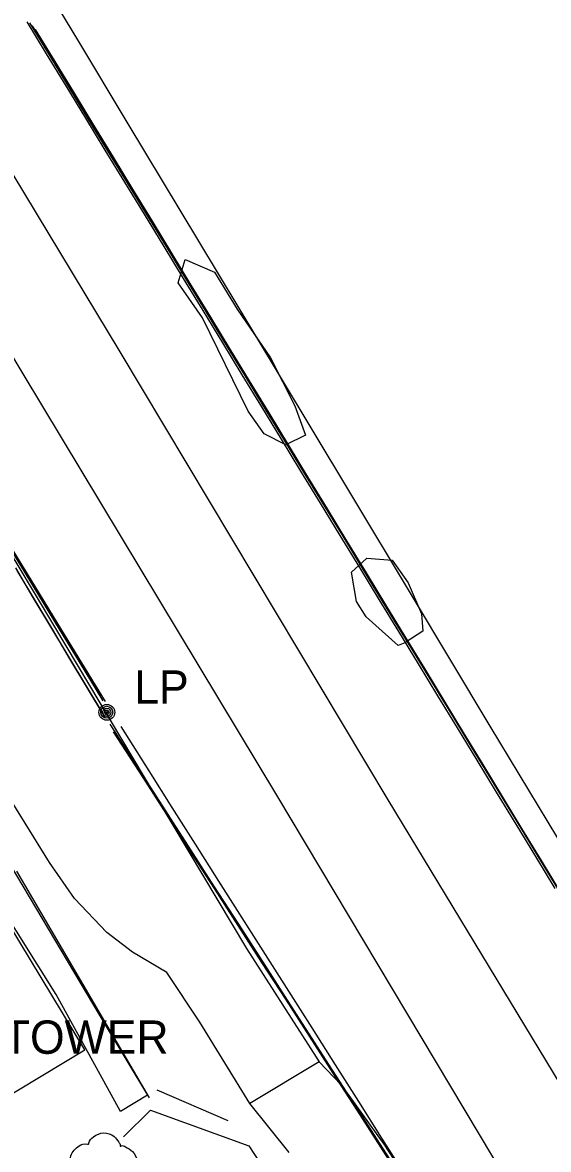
# Model space of a CAD drawing. Extents: x 368532 to 392481, y 10654822 to 10676899.
# Drawn here: x 378958.9 to 379037.9, y 10660853.5 to 10661022.5 of the extents above; entities that cross this region are included whole.
import ezdxf

# ---------------------------------------------------------------- set-up
doc = ezdxf.new("R2010")
doc.units = 0
for name, color, linetype in [('p_Catenary', 7, 'Continuous'), ('p_dtm retaining wall', 7, 'Continuous'), ('p_dtm sidewalk', 7, 'Continuous'), ('p_railroad rr control', 7, 'Continuous'), ('p_road - paved curb', 7, 'Continuous'), ('p_road conc barrier', 7, 'Continuous'), ('p_road dirt road', 7, 'Continuous'), ('p_road general road feature', 7, 'Continuous'), ('p_structure fence', 7, 'Continuous'), ('p_structure general', 7, 'Continuous'), ('p_utility general pole', 7, 'Continuous'), ('p_veg tree', 7, 'Continuous'), ('p_veg woods', 7, 'Continuous')]:
    doc.layers.add(name, color=color, linetype=linetype)

msp = doc.modelspace()

# ---------------------------------------------------------------- linework, layer by layer
at = {"layer": 'p_Catenary'}
for points in [[(378971.06, 10660920.8), (378967.51, 10660926.63), (378963.95, 10660932.46), (378960.4, 10660938.29), (378956.85, 10660944.12), (378953.29, 10660949.95), (378949.74, 10660955.79), (378946.19, 10660961.62), (378942.64, 10660967.45), (378939.08, 10660973.28), (378935.53, 10660979.11), (378931.98, 10660984.94), (378928.42, 10660990.78), (378924.87, 10660996.61), (378921.32, 10661002.44), (378917.76, 10661008.27), (378914.21, 10661014.1), (378910.66, 10661019.94), (378907.1, 10661025.77)], [(378970.65, 10660921.48), (378967.13, 10660927.25), (378963.62, 10660933.01), (378960.1, 10660938.78), (378956.59, 10660944.55), (378953.07, 10660950.32), (378949.56, 10660956.09), (378946.04, 10660961.86), (378942.53, 10660967.63), (378939.01, 10660973.4), (378935.5, 10660979.17), (378931.98, 10660984.94), (378928.47, 10660990.71), (378924.95, 10660996.48), (378921.44, 10661002.24), (378917.92, 10661008.01), (378914.41, 10661013.78), (378910.89, 10661019.55), (378907.37, 10661025.32)], [(378907.77, 10661024.85), (378911.3, 10661019.06), (378914.83, 10661013.27), (378918.36, 10661007.49), (378921.89, 10661001.7), (378925.42, 10660995.91), (378928.95, 10660990.13), (378932.48, 10660984.34), (378936.01, 10660978.56), (378939.54, 10660972.77), (378943.07, 10660966.98), (378946.6, 10660961.2), (378950.13, 10660955.41), (378953.66, 10660949.62), (378957.19, 10660943.84), (378960.72, 10660938.05), (378964.25, 10660932.27), (378967.78, 10660926.48), (378971.32, 10660920.69)], [(378959.56, 10661022.63), (378962.5, 10661017.82), (378965.44, 10661013.01), (378968.37, 10661008.19), (378971.31, 10661003.38), (378974.25, 10660998.57), (378977.18, 10660993.75), (378980.12, 10660988.94), (378983.06, 10660984.12), (378985.99, 10660979.31), (378988.93, 10660974.5), (378991.87, 10660969.68), (378994.8, 10660964.87), (378997.74, 10660960.05), (379000.68, 10660955.24), (379003.61, 10660950.43), (379006.55, 10660945.61), (379009.49, 10660940.8), (379012.42, 10660935.98), (379015.36, 10660931.17), (379018.3, 10660926.36), (379021.23, 10660921.54), (379024.17, 10660916.73), (379027.11, 10660911.91), (379030.04, 10660907.1), (379032.98, 10660902.29), (379035.92, 10660897.47), (379038.85, 10660892.66)], [(378959.98, 10661022.47), (378962.91, 10661017.67), (378965.84, 10661012.88), (378968.76, 10661008.08), (378971.69, 10661003.29), (378974.62, 10660998.49), (378977.55, 10660993.7), (378980.48, 10660988.9), (378983.41, 10660984.11), (378986.34, 10660979.31), (378989.26, 10660974.52), (378992.19, 10660969.72), (378995.12, 10660964.93), (378998.05, 10660960.13), (379000.98, 10660955.34), (379003.91, 10660950.54), (379006.84, 10660945.75), (379009.76, 10660940.95), (379012.69, 10660936.16), (379015.62, 10660931.36), (379018.55, 10660926.57), (379021.48, 10660921.77), (379024.41, 10660916.98), (379027.34, 10660912.18), (379030.26, 10660907.39), (379033.19, 10660902.59), (379036.12, 10660897.8), (379039.05, 10660893)], [(378960.36, 10661022.03), (378977.78, 10660993.45), (378981.24, 10660987.79), (378984.69, 10660982.12), (378988.14, 10660976.46), (378991.6, 10660970.8), (378995.05, 10660965.13), (378998.5, 10660959.47), (379001.96, 10660953.81), (379005.41, 10660948.14), (379008.86, 10660942.48), (379012.32, 10660936.82), (379015.77, 10660931.15), (379019.22, 10660925.49), (379022.68, 10660919.83), (379026.13, 10660914.16), (379029.58, 10660908.5), (379033.04, 10660902.84), (379036.49, 10660897.17), (379039.94, 10660891.51)], [(378960.85, 10661021.48), (378963.77, 10661016.69), (378966.69, 10661011.9), (378969.61, 10661007.1), (378972.53, 10661002.31), (378975.45, 10660997.52), (378978.37, 10660992.73), (378981.29, 10660987.93), (378984.21, 10660983.14), (378987.13, 10660978.35), (378990.05, 10660973.55), (378992.97, 10660968.76), (378995.89, 10660963.97), (378998.81, 10660959.17), (379001.73, 10660954.38), (379004.65, 10660949.59), (379007.57, 10660944.79), (379010.49, 10660940), (379013.41, 10660935.21), (379016.33, 10660930.42), (379019.25, 10660925.62), (379022.17, 10660920.83), (379025.09, 10660916.04), (379028.01, 10660911.24), (379030.93, 10660906.45), (379033.85, 10660901.66), (379036.77, 10660896.86), (379039.7, 10660892.07)], [(378957.86, 10660940.72), (378960.5, 10660936.31), (378963.14, 10660931.9), (378965.79, 10660927.5), (378968.43, 10660923.09), (378971.07, 10660918.69)], [(378958.06, 10660940.34), (378960.71, 10660935.93), (378963.36, 10660931.52), (378966.01, 10660927.1), (378968.66, 10660922.69), (378971.3, 10660918.28)], [(378972.02, 10660917.29), (378975.73, 10660911.53), (378979.45, 10660905.76), (378983.16, 10660899.99), (378986.87, 10660894.22), (378990.58, 10660888.46), (378994.29, 10660882.69), (378998, 10660876.92), (379001.72, 10660871.16), (379005.43, 10660865.39), (379009.14, 10660859.62), (379012.85, 10660853.85), (379016.56, 10660848.09), (379020.28, 10660842.32), (379023.99, 10660836.55), (379027.7, 10660830.78), (379031.41, 10660825.02), (379035.12, 10660819.25), (379038.83, 10660813.48)], [(378972.67, 10660916.27), (378976.39, 10660910.51), (378980.1, 10660904.74), (378983.81, 10660898.98), (378987.52, 10660893.21), (378991.23, 10660887.45), (378994.95, 10660881.68), (378998.66, 10660875.91), (379002.37, 10660870.15), (379006.08, 10660864.38), (379009.79, 10660858.62), (379013.51, 10660852.85), (379017.22, 10660847.09), (379020.93, 10660841.32), (379024.64, 10660835.55), (379028.35, 10660829.79), (379032.07, 10660824.02), (379035.78, 10660818.26), (379039.49, 10660812.49)], [(378973.67, 10660916.92), (378977.87, 10660910.3), (378981.36, 10660904.79), (378984.86, 10660899.28), (378988.36, 10660893.77), (378991.86, 10660888.26), (378995.35, 10660882.75), (378998.85, 10660877.24), (379002.35, 10660871.73), (379005.85, 10660866.22), (379009.34, 10660860.71), (379012.84, 10660855.2), (379016.34, 10660849.69), (379019.83, 10660844.18), (379023.33, 10660838.67), (379026.83, 10660833.16), (379030.33, 10660827.65), (379033.82, 10660822.14), (379037.32, 10660816.63), (379040.82, 10660811.12)], [(378972.55, 10660916.16), (378976.98, 10660909.28), (378980.55, 10660903.74), (378984.12, 10660898.2), (378987.69, 10660892.66), (378991.25, 10660887.12), (378994.82, 10660881.57), (378998.39, 10660876.03), (379001.96, 10660870.49), (379005.53, 10660864.95), (379009.1, 10660859.41), (379012.66, 10660853.86), (379016.23, 10660848.32), (379019.8, 10660842.78), (379023.37, 10660837.24), (379026.94, 10660831.7), (379030.51, 10660826.15), (379034.07, 10660820.61), (379037.64, 10660815.07), (379041.21, 10660809.53)], [(378972.96, 10660915.8), (378976.67, 10660910.04), (378980.38, 10660904.28), (378984.08, 10660898.51), (378987.79, 10660892.75), (378991.5, 10660886.99), (378995.21, 10660881.23), (378998.91, 10660875.46), (379002.62, 10660869.7), (379006.33, 10660863.94), (379010.04, 10660858.18), (379013.74, 10660852.41), (379017.45, 10660846.65), (379021.16, 10660840.89), (379024.87, 10660835.13), (379028.57, 10660829.36), (379032.28, 10660823.6), (379035.99, 10660817.84), (379039.7, 10660812.08)]]:
    msp.add_lwpolyline(points, dxfattribs=at)
at = {"layer": 'p_dtm retaining wall'}
for p, q in [((378967.38, 10661019.66), (378955.97, 10661038.61)), ((378974.64, 10661007.59), (378967.38, 10661019.66)), ((378985.39, 10660989.73), (378974.64, 10661007.59)), ((378997.19, 10660970.12), (378985.39, 10660989.73)), ((379008.04, 10660952.09), (378997.19, 10660970.12)), ((379017.3, 10660936.7), (379008.04, 10660952.09)), ((379029.15, 10660917.01), (379017.3, 10660936.7)), ((379040.72, 10660897.79), (379029.15, 10660917.01))]:
    msp.add_line(p, q, dxfattribs=at)
at = {"layer": 'p_dtm sidewalk'}
for p, q in [((378954.97, 10660899.71), (378971.34, 10660872.21)), ((378963.99, 10660876.73), (378954.22, 10660892.29)), ((378973.64, 10660859.23), (378963.99, 10660876.73)), ((378971.34, 10660872.21), (378977.67, 10660861.66)), ((378977.67, 10660861.66), (378973.64, 10660859.23))]:
    msp.add_line(p, q, dxfattribs=at)
at = {"layer": 'p_railroad rr control'}
for points in [[(378865.62, 10661153.05), (378897.1, 10661100.38), (378934.06, 10661038.48), (378973.54, 10660973.11), (379013.78, 10660905.94), (379052.64, 10660841.8), (379087.1, 10660784.56), (379120.73, 10660728.31), (379144.4, 10660688.64)], [(379130.1, 10660685.16), (379100.83, 10660734.15), (379065.82, 10660792.43), (379029.67, 10660852.15), (378997.09, 10660906.64), (378959.05, 10660969.85), (378921.51, 10661032.58), (378886.59, 10661091.01), (378851.09, 10661149.9)]]:
    msp.add_lwpolyline(points, dxfattribs=at)
at = {"layer": 'p_road - paved curb'}
for p, q in [((378950.95, 10660953.22), (378963.72, 10660931.91)), ((378963.72, 10660931.91), (378977.2, 10660909.34)), ((378962.96, 10660896.55), (378955.66, 10660908.36)), ((378977.2, 10660909.34), (378992.57, 10660883.64)), ((378966.74, 10660891.17), (378962.96, 10660896.55)), ((378971.57, 10660886.06), (378966.74, 10660891.17)), ((378975.44, 10660883.11), (378971.57, 10660886.06)), ((378980.59, 10660880.05), (378975.44, 10660883.11)), ((378992.57, 10660883.64), (379003.48, 10660866.64)), ((378985.54, 10660872.62), (378980.59, 10660880.05)), ((378993.04, 10660860.39), (378985.54, 10660872.62)), ((379003.48, 10660866.64), (378993.04, 10660860.39))]:
    msp.add_line(p, q, dxfattribs=at)
at = {"layer": 'p_road conc barrier'}
for p, q in [((378977.98, 10660861.26), (378958.1, 10660895.26)), ((378989.79, 10660857.8), (378979.13, 10660862.4))]:
    msp.add_line(p, q, dxfattribs=at)
at = {"layer": 'p_road dirt road'}
for p, q in [((379003.48, 10660866.64), (379006.74, 10660863.21)), ((379006.74, 10660863.21), (379013.16, 10660854.32)), ((378998.95, 10660853.06), (378993.04, 10660860.39)), ((379013.16, 10660854.32), (379026.09, 10660834.64))]:
    msp.add_line(p, q, dxfattribs=at)
at = {"layer": 'p_road general road feature'}
for p, q in [((378968.27, 10660868.43), (378954.58, 10660891.08)), ((378950.99, 10660858.09), (378968.27, 10660868.43))]:
    msp.add_line(p, q, dxfattribs=at)
at = {"layer": 'p_structure fence'}
for p, q in [((378974.09, 10660855.43), (378978.13, 10660859.4)), ((378978.13, 10660859.4), (378992.91, 10660854.07)), ((378992.91, 10660854.07), (379019.42, 10660813.85))]:
    msp.add_line(p, q, dxfattribs=at)
at = {"layer": 'p_utility general pole'}
for radius in [1.19, 0.901, 0.608, 0.337, 0.12]:
    msp.add_circle((378971.58, 10660919.07), radius, dxfattribs=at)
at = {"layer": 'p_veg tree'}
msp.add_spline([(378970.81, 10660846.75), (378969.31, 10660846.31), (378967.8, 10660846.88), (378967.03, 10660848.17), (378966.89, 10660849.01), (378967.05, 10660849.7), (378967.12, 10660849.83), (378967.03, 10660849.9), (378966.42, 10660850.64), (378966.21, 10660852.56), (378967.42, 10660854.04), (378968.69, 10660854.33), (378968.84, 10660854.33), (378968.88, 10660854.44), (378969.6, 10660855.42), (378971.11, 10660856), (378972.69, 10660855.46), (378973.38, 10660854.61), (378973.6, 10660854.11), (378973.61, 10660853.99), (378973.71, 10660854.03), (378974.37, 10660853.91), (378975.45, 10660853.22), (378976.11, 10660851.79), (378975.86, 10660850.42), (378975.12, 10660849.56), (378974.89, 10660849.43), (378974.86, 10660849.36), (378974.87, 10660849.3), (378974.94, 10660848.85), (378974.88, 10660847.88), (378974.2, 10660846.87), (378973.12, 10660846.22), (378971.53, 10660846.32), (378970.78, 10660846.75)], degree=3, dxfattribs=at)
at = {"layer": 'p_veg woods'}
for points in [[(378985.95, 10660978.25), (378982.28, 10660983.5), (378983.36, 10660986.98), (378987.77, 10660985.07), (378991.17, 10660979.53), (378996.15, 10660972.23), (378999.83, 10660965.05), (379001.43, 10660960.62), (378998.44, 10660959.18), (378995.19, 10660960.85), (378992.82, 10660964.21)], [(379010.53, 10660933.37), (379009.06, 10660935.7), (379008.33, 10660940.09), (379010.61, 10660942.17), (379014.41, 10660941.88), (379016.84, 10660938.48), (379018.83, 10660933.84), (379019, 10660931.23), (379016.3, 10660929.48), (379015.31, 10660929.07)]]:
    msp.add_lwpolyline(points, close=True, dxfattribs=at)

# ---------------------------------------------------------------- texts
at = {"layer": 'p_structure general'}
msp.add_text('CELL TOWER', height=5, dxfattribs=at).set_placement((378937.39, 10660867.86))
at = {"layer": 'p_utility general pole'}
msp.add_text('LP', height=5, dxfattribs=at).set_placement((378975.7, 10660920.36))

doc.saveas('drawing.dxf')
